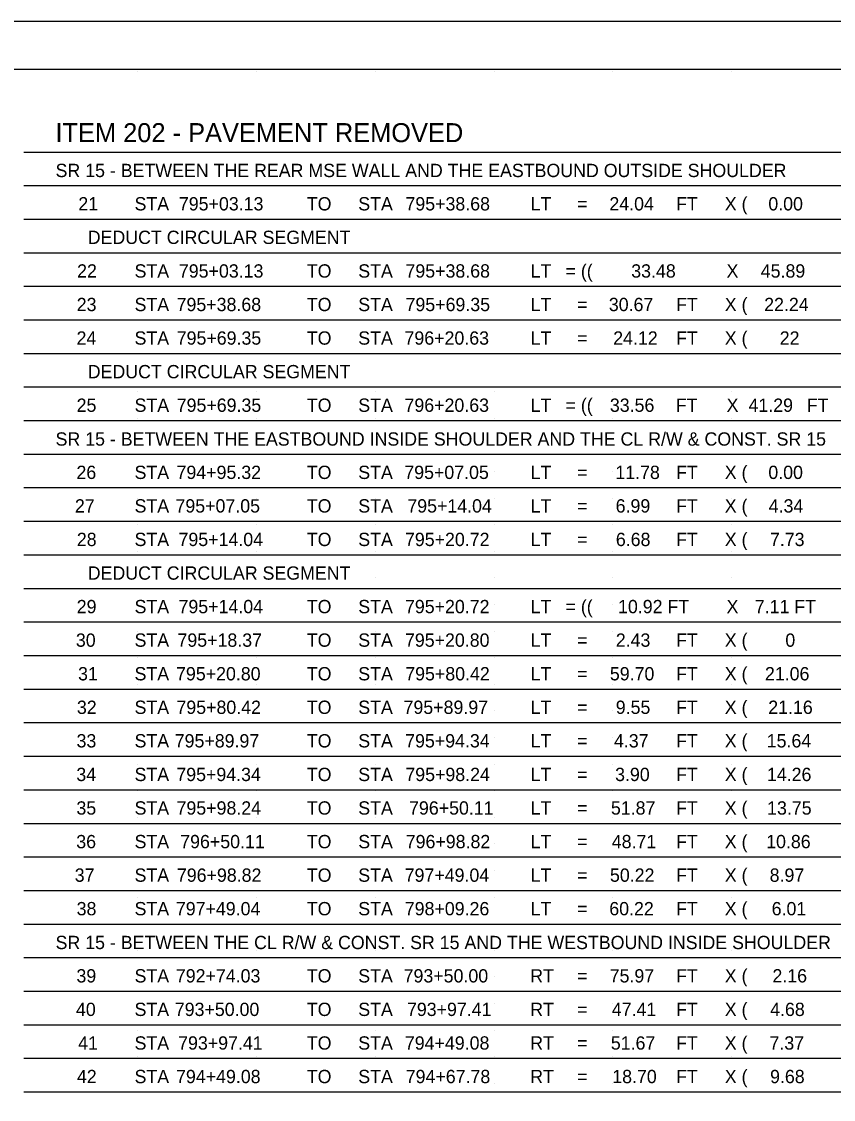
# Model space of a CAD drawing. Extents: x 2073163.5 to 2073197.5, y 634076.4 to 634098.4.
# Drawn here: x 2073180.34 to 2073188.9, y 634087.09 to 634098.43 of the extents above; entities that cross this region are included whole.
import ezdxf

# ---------------------------------------------------------------- set-up
doc = ezdxf.new("R2010")
doc.units = 0
for name, color, linetype in [('SC_Scratch1', 7, 'Continuous'), ('SH_Border', 7, 'Continuous'), ('SH_Cut_Line', 7, 'Continuous'), ('SH_Data', 7, 'Continuous'), ('SH_Text', 7, 'Continuous')]:
    doc.layers.add(name, color=color, linetype=linetype)

msp = doc.modelspace()

# ---------------------------------------------------------------- linework, layer by layer
at = {"layer": 'SC_Scratch1'}
for p, q in [((2073180.369, 634097.061), (2073194.796, 634097.061)), ((2073180.369, 634096.708), (2073194.796, 634096.708)), ((2073180.369, 634096.354), (2073194.796, 634096.354)), ((2073180.369, 634096.001), (2073194.796, 634096.001)), ((2073180.369, 634095.648), (2073194.796, 634095.648)), ((2073180.369, 634095.294), (2073194.796, 634095.294)), ((2073180.369, 634094.941), (2073194.796, 634094.941)), ((2073180.369, 634094.588), (2073194.796, 634094.588)), ((2073180.369, 634094.234), (2073194.796, 634094.234)), ((2073180.369, 634093.881), (2073194.796, 634093.881)), ((2073180.369, 634093.528), (2073194.796, 634093.528)), ((2073180.369, 634093.174), (2073194.796, 634093.174)), ((2073180.369, 634092.821), (2073194.796, 634092.821)), ((2073180.369, 634092.468), (2073194.796, 634092.468)), ((2073180.369, 634092.114), (2073194.796, 634092.114)), ((2073180.369, 634091.761), (2073194.796, 634091.761)), ((2073180.369, 634091.407), (2073194.796, 634091.407)), ((2073180.369, 634091.054), (2073194.796, 634091.054)), ((2073180.369, 634090.701), (2073194.796, 634090.701)), ((2073180.369, 634090.347), (2073194.796, 634090.347)), ((2073180.369, 634089.994), (2073194.796, 634089.994)), ((2073180.369, 634089.641), (2073194.796, 634089.641)), ((2073180.369, 634089.287), (2073194.796, 634089.287)), ((2073180.369, 634088.934), (2073194.796, 634088.934)), ((2073180.369, 634088.581), (2073194.796, 634088.581)), ((2073180.369, 634088.227), (2073194.796, 634088.227)), ((2073180.369, 634087.874), (2073194.796, 634087.874)), ((2073180.369, 634087.521), (2073194.796, 634087.521)), ((2073180.369, 634087.167), (2073194.796, 634087.167))]:
    msp.add_line(p, q, dxfattribs=at)
at = {"layer": 'SH_Border'}
msp.add_lwpolyline([(2073165.007, 634097.934), (2073197.007, 634097.934), (2073197.007, 634076.934), (2073165.007, 634076.934)], close=True, dxfattribs=at)
at = {"layer": 'SH_Cut_Line'}
msp.add_lwpolyline([(2073163.507, 634076.434), (2073197.507, 634076.434), (2073197.507, 634098.434), (2073163.507, 634098.434)], close=True, dxfattribs=at)
at = {"layer": 'SH_Data'}
for p, q in [((2073181.571, 634097.91), (2073181.571, 634097.91)), ((2073181.571, 634097.91), (2073181.571, 634097.91)), ((2073182.821, 634097.91), (2073182.821, 634097.91)), ((2073182.821, 634097.91), (2073182.821, 634097.91)), ((2073182.821, 634097.91), (2073182.821, 634097.91)), ((2073184.071, 634097.91), (2073184.071, 634097.91)), ((2073184.071, 634097.91), (2073184.071, 634097.91)), ((2073184.071, 634097.91), (2073184.071, 634097.91)), ((2073184.071, 634097.91), (2073184.071, 634097.91)), ((2073185.321, 634097.91), (2073185.321, 634097.91)), ((2073185.321, 634097.91), (2073185.321, 634097.91)), ((2073185.321, 634097.91), (2073185.321, 634097.91)), ((2073185.321, 634097.91), (2073185.321, 634097.91)), ((2073185.321, 634097.91), (2073185.321, 634097.91)), ((2073186.571, 634097.91), (2073186.571, 634097.91)), ((2073187.821, 634097.91), (2073187.821, 634097.91)), ((2073181.571, 634094.538), (2073181.571, 634094.538)), ((2073181.571, 634094.538), (2073181.571, 634094.538)), ((2073182.821, 634094.538), (2073182.821, 634094.538)), ((2073182.821, 634094.538), (2073182.821, 634094.538)), ((2073182.821, 634094.538), (2073182.821, 634094.538)), ((2073184.071, 634094.538), (2073184.071, 634094.538)), ((2073184.071, 634094.538), (2073184.071, 634094.538)), ((2073184.071, 634094.538), (2073184.071, 634094.538)), ((2073184.071, 634094.538), (2073184.071, 634094.538)), ((2073185.321, 634094.538), (2073185.321, 634094.538)), ((2073185.321, 634094.538), (2073185.321, 634094.538)), ((2073185.321, 634094.538), (2073185.321, 634094.538)), ((2073185.321, 634094.538), (2073185.321, 634094.538)), ((2073185.321, 634094.538), (2073185.321, 634094.538)), ((2073186.571, 634094.538), (2073186.571, 634094.538)), ((2073187.821, 634094.538), (2073187.821, 634094.538)), ((2073181.571, 634094.258), (2073181.571, 634094.258)), ((2073182.821, 634094.258), (2073182.821, 634094.258)), ((2073184.071, 634094.258), (2073184.071, 634094.258)), ((2073185.321, 634094.258), (2073185.321, 634094.258)), ((2073186.571, 634094.258), (2073186.571, 634094.258)), ((2073187.821, 634094.258), (2073187.821, 634094.258)), ((2073181.571, 634093.978), (2073181.571, 634093.978)), ((2073182.821, 634093.978), (2073182.821, 634093.978)), ((2073184.071, 634093.978), (2073184.071, 634093.978)), ((2073185.321, 634093.978), (2073185.321, 634093.978)), ((2073186.571, 634093.978), (2073186.571, 634093.978)), ((2073187.821, 634093.978), (2073187.821, 634093.978)), ((2073181.571, 634093.698), (2073181.571, 634093.698)), ((2073182.821, 634093.698), (2073182.821, 634093.698)), ((2073184.071, 634093.698), (2073184.071, 634093.698)), ((2073185.321, 634093.698), (2073185.321, 634093.698)), ((2073186.571, 634093.698), (2073186.571, 634093.698)), ((2073187.821, 634093.698), (2073187.821, 634093.698)), ((2073181.571, 634093.418), (2073181.571, 634093.418)), ((2073182.821, 634093.418), (2073182.821, 634093.418)), ((2073184.071, 634093.418), (2073184.071, 634093.418)), ((2073185.321, 634093.418), (2073185.321, 634093.418)), ((2073186.571, 634093.418), (2073186.571, 634093.418)), ((2073187.821, 634093.418), (2073187.821, 634093.418)), ((2073181.571, 634093.138), (2073181.571, 634093.138)), ((2073182.821, 634093.138), (2073182.821, 634093.138)), ((2073184.071, 634093.138), (2073184.071, 634093.138)), ((2073185.321, 634093.138), (2073185.321, 634093.138)), ((2073186.571, 634093.138), (2073186.571, 634093.138)), ((2073187.821, 634093.138), (2073187.821, 634093.138)), ((2073181.571, 634092.858), (2073181.571, 634092.858)), ((2073182.821, 634092.858), (2073182.821, 634092.858)), ((2073184.071, 634092.858), (2073184.071, 634092.858)), ((2073185.321, 634092.858), (2073185.321, 634092.858)), ((2073186.571, 634092.858), (2073186.571, 634092.858)), ((2073187.821, 634092.858), (2073187.821, 634092.858)), ((2073181.571, 634092.578), (2073181.571, 634092.578)), ((2073182.821, 634092.578), (2073182.821, 634092.578)), ((2073184.071, 634092.578), (2073184.071, 634092.578)), ((2073185.321, 634092.578), (2073185.321, 634092.578)), ((2073186.571, 634092.578), (2073186.571, 634092.578)), ((2073187.821, 634092.578), (2073187.821, 634092.578)), ((2073181.571, 634092.298), (2073181.571, 634092.298)), ((2073182.821, 634092.298), (2073182.821, 634092.298)), ((2073184.071, 634092.298), (2073184.071, 634092.298)), ((2073185.321, 634092.298), (2073185.321, 634092.298)), ((2073186.571, 634092.298), (2073186.571, 634092.298)), ((2073187.821, 634092.298), (2073187.821, 634092.298)), ((2073181.571, 634092.018), (2073181.571, 634092.018)), ((2073182.821, 634092.018), (2073182.821, 634092.018)), ((2073184.071, 634092.018), (2073184.071, 634092.018)), ((2073185.321, 634092.018), (2073185.321, 634092.018)), ((2073186.571, 634092.018), (2073186.571, 634092.018)), ((2073187.821, 634092.018), (2073187.821, 634092.018)), ((2073181.571, 634091.738), (2073181.571, 634091.738)), ((2073182.821, 634091.738), (2073182.821, 634091.738)), ((2073184.071, 634091.738), (2073184.071, 634091.738)), ((2073185.321, 634091.738), (2073185.321, 634091.738)), ((2073186.571, 634091.738), (2073186.571, 634091.738)), ((2073187.821, 634091.738), (2073187.821, 634091.738)), ((2073181.571, 634091.458), (2073181.571, 634091.458)), ((2073182.821, 634091.458), (2073182.821, 634091.458)), ((2073184.071, 634091.458), (2073184.071, 634091.458)), ((2073185.321, 634091.458), (2073185.321, 634091.458)), ((2073186.571, 634091.458), (2073186.571, 634091.458)), ((2073187.821, 634091.458), (2073187.821, 634091.458)), ((2073181.571, 634091.178), (2073181.571, 634091.178)), ((2073182.821, 634091.178), (2073182.821, 634091.178)), ((2073184.071, 634091.178), (2073184.071, 634091.178)), ((2073185.321, 634091.178), (2073185.321, 634091.178)), ((2073186.571, 634091.178), (2073186.571, 634091.178)), ((2073187.821, 634091.178), (2073187.821, 634091.178)), ((2073181.571, 634090.898), (2073181.571, 634090.898)), ((2073182.821, 634090.898), (2073182.821, 634090.898)), ((2073184.071, 634090.898), (2073184.071, 634090.898)), ((2073185.321, 634090.898), (2073185.321, 634090.898)), ((2073186.571, 634090.898), (2073186.571, 634090.898)), ((2073187.821, 634090.898), (2073187.821, 634090.898)), ((2073181.571, 634090.618), (2073181.571, 634090.618)), ((2073182.821, 634090.618), (2073182.821, 634090.618)), ((2073184.071, 634090.618), (2073184.071, 634090.618)), ((2073185.321, 634090.618), (2073185.321, 634090.618)), ((2073186.571, 634090.618), (2073186.571, 634090.618)), ((2073187.821, 634090.618), (2073187.821, 634090.618)), ((2073181.571, 634090.338), (2073181.571, 634090.338)), ((2073182.821, 634090.338), (2073182.821, 634090.338)), ((2073184.071, 634090.338), (2073184.071, 634090.338)), ((2073185.321, 634090.338), (2073185.321, 634090.338)), ((2073186.571, 634090.338), (2073186.571, 634090.338)), ((2073187.821, 634090.338), (2073187.821, 634090.338)), ((2073181.571, 634090.058), (2073181.571, 634090.058)), ((2073182.821, 634090.058), (2073182.821, 634090.058)), ((2073184.071, 634090.058), (2073184.071, 634090.058)), ((2073185.321, 634090.058), (2073185.321, 634090.058)), ((2073186.571, 634090.058), (2073186.571, 634090.058)), ((2073187.821, 634090.058), (2073187.821, 634090.058)), ((2073181.571, 634089.778), (2073181.571, 634089.778)), ((2073182.821, 634089.778), (2073182.821, 634089.778)), ((2073184.071, 634089.778), (2073184.071, 634089.778)), ((2073185.321, 634089.778), (2073185.321, 634089.778)), ((2073186.571, 634089.778), (2073186.571, 634089.778)), ((2073187.821, 634089.778), (2073187.821, 634089.778)), ((2073181.571, 634089.498), (2073181.571, 634089.498)), ((2073182.821, 634089.498), (2073182.821, 634089.498)), ((2073184.071, 634089.498), (2073184.071, 634089.498)), ((2073185.321, 634089.498), (2073185.321, 634089.498)), ((2073186.571, 634089.498), (2073186.571, 634089.498)), ((2073187.821, 634089.498), (2073187.821, 634089.498)), ((2073181.571, 634089.218), (2073181.571, 634089.218)), ((2073182.821, 634089.218), (2073182.821, 634089.218)), ((2073184.071, 634089.218), (2073184.071, 634089.218)), ((2073185.321, 634089.218), (2073185.321, 634089.218)), ((2073186.571, 634089.218), (2073186.571, 634089.218)), ((2073187.821, 634089.218), (2073187.821, 634089.218)), ((2073181.571, 634088.938), (2073181.571, 634088.938)), ((2073182.821, 634088.938), (2073182.821, 634088.938)), ((2073184.071, 634088.938), (2073184.071, 634088.938)), ((2073185.321, 634088.938), (2073185.321, 634088.938)), ((2073186.571, 634088.938), (2073186.571, 634088.938)), ((2073187.821, 634088.938), (2073187.821, 634088.938)), ((2073181.571, 634088.658), (2073181.571, 634088.658)), ((2073182.821, 634088.658), (2073182.821, 634088.658)), ((2073184.071, 634088.658), (2073184.071, 634088.658)), ((2073185.321, 634088.658), (2073185.321, 634088.658)), ((2073186.571, 634088.658), (2073186.571, 634088.658)), ((2073187.821, 634088.658), (2073187.821, 634088.658)), ((2073181.571, 634088.378), (2073181.571, 634088.378)), ((2073182.821, 634088.378), (2073182.821, 634088.378)), ((2073184.071, 634088.378), (2073184.071, 634088.378)), ((2073185.321, 634088.378), (2073185.321, 634088.378)), ((2073186.571, 634088.378), (2073186.571, 634088.378)), ((2073187.821, 634088.378), (2073187.821, 634088.378)), ((2073181.571, 634088.098), (2073181.571, 634088.098)), ((2073182.821, 634088.098), (2073182.821, 634088.098)), ((2073184.071, 634088.098), (2073184.071, 634088.098)), ((2073185.321, 634088.098), (2073185.321, 634088.098)), ((2073186.571, 634088.098), (2073186.571, 634088.098)), ((2073187.821, 634088.098), (2073187.821, 634088.098)), ((2073181.571, 634087.818), (2073181.571, 634087.818)), ((2073182.821, 634087.818), (2073182.821, 634087.818)), ((2073184.071, 634087.818), (2073184.071, 634087.818)), ((2073185.321, 634087.818), (2073185.321, 634087.818)), ((2073186.571, 634087.818), (2073186.571, 634087.818)), ((2073187.821, 634087.818), (2073187.821, 634087.818)), ((2073181.571, 634087.538), (2073181.571, 634087.538)), ((2073182.821, 634087.538), (2073182.821, 634087.538)), ((2073184.071, 634087.538), (2073184.071, 634087.538)), ((2073185.321, 634087.538), (2073185.321, 634087.538)), ((2073186.571, 634087.538), (2073186.571, 634087.538)), ((2073187.821, 634087.538), (2073187.821, 634087.538)), ((2073181.571, 634087.258), (2073181.571, 634087.258)), ((2073182.821, 634087.258), (2073182.821, 634087.258)), ((2073184.071, 634087.258), (2073184.071, 634087.258)), ((2073185.321, 634087.258), (2073185.321, 634087.258)), ((2073186.571, 634087.258), (2073186.571, 634087.258)), ((2073187.821, 634087.258), (2073187.821, 634087.258))]:
    msp.add_line(p, q, dxfattribs=at)

# ---------------------------------------------------------------- texts
msp.add_text('ITEM 202 - PAVEMENT REMOVED', height=0.2, dxfattribs=at).set_placement((2073180.702, 634097.165))
at = {"layer": 'SH_Text'}
for s, p in [('SR 15 - BETWEEN THE REAR MSE WALL AND THE EASTBOUND OUTSIDE SHOULDER', (2073180.703, 634096.797)), ('21', (2073180.943, 634096.446)), ('STA', (2073181.535, 634096.446)), ('795+03.13', (2073182.002, 634096.446)), ('TO', (2073183.349, 634096.446)), ('STA', (2073183.891, 634096.446)), ('795+38.68', (2073184.388, 634096.446)), ('LT', (2073185.706, 634096.446)), ('=', (2073186.196, 634096.446)), ('24.04', (2073186.536, 634096.446)), ('FT', (2073187.238, 634096.446)), ('X (', (2073187.751, 634096.446)), ('0.00', (2073188.21, 634096.446)), ('DEDUCT CIRCULAR SEGMENT', (2073181.042, 634096.093)), ('22', (2073180.93, 634095.739)), ('STA', (2073181.535, 634095.739)), ('795+03.13', (2073182.002, 634095.739)), ('TO', (2073183.349, 634095.739)), ('STA', (2073183.891, 634095.739)), ('795+38.68', (2073184.388, 634095.739)), ('LT', (2073185.706, 634095.739)), ('= ((', (2073186.074, 634095.739)), ('33.48', (2073186.766, 634095.739)), ('X', (2073187.77, 634095.739)), ('45.89', (2073188.13, 634095.739)), ('23', (2073180.926, 634095.386)), ('STA', (2073181.535, 634095.386)), ('795+38.68', (2073181.978, 634095.386)), ('TO', (2073183.349, 634095.386)), ('STA', (2073183.891, 634095.386)), ('795+69.35', (2073184.389, 634095.386)), ('LT', (2073185.706, 634095.386)), ('=', (2073186.196, 634095.386)), ('30.67', (2073186.53, 634095.386)), ('FT', (2073187.238, 634095.386)), ('X (', (2073187.751, 634095.386)), ('22.24', (2073188.166, 634095.386)), ('24', (2073180.924, 634095.033)), ('STA', (2073181.535, 634095.033)), ('795+69.35', (2073181.979, 634095.033)), ('TO', (2073183.349, 634095.033)), ('STA', (2073183.891, 634095.033)), ('796+20.63', (2073184.378, 634095.033)), ('LT', (2073185.706, 634095.033)), ('24.12', (2073186.576, 634095.033)), ('FT', (2073187.238, 634095.033)), ('X (', (2073187.751, 634095.033)), ('22', (2073188.33, 634095.033)), ('=', (2073186.196, 634095.033)), ('DEDUCT CIRCULAR SEGMENT', (2073181.042, 634094.679)), ('25', (2073180.925, 634094.326)), ('STA', (2073181.535, 634094.326)), ('795+69.35', (2073181.979, 634094.326)), ('TO', (2073183.349, 634094.326)), ('STA', (2073183.891, 634094.326)), ('796+20.63', (2073184.378, 634094.326)), ('LT', (2073185.706, 634094.326)), ('= ((', (2073186.074, 634094.326)), ('33.56', (2073186.541, 634094.326)), ('FT', (2073187.235, 634094.326)), ('X', (2073187.77, 634094.326)), ('41.29', (2073188.001, 634094.326)), ('FT', (2073188.615, 634094.326)), ('SR 15 - BETWEEN THE EASTBOUND INSIDE SHOULDER AND THE CL R/W & CONST. SR 15', (2073180.703, 634093.97)), ('26', (2073180.923, 634093.619)), ('STA', (2073181.535, 634093.619)), ('794+95.32', (2073181.977, 634093.619)), ('TO', (2073183.349, 634093.619)), ('STA', (2073183.891, 634093.619)), ('795+07.05', (2073184.376, 634093.619)), ('LT', (2073185.706, 634093.619)), ('=', (2073186.196, 634093.619)), ('11.78', (2073186.599, 634093.619)), ('FT', (2073187.238, 634093.619)), ('X (', (2073187.751, 634093.619)), ('0.00', (2073188.21, 634093.619)), ('27', (2073180.907, 634093.266)), ('STA', (2073181.535, 634093.266)), ('795+07.05', (2073181.966, 634093.266)), ('TO', (2073183.349, 634093.266)), ('STA', (2073183.891, 634093.266)), ('795+14.04', (2073184.408, 634093.266)), ('LT', (2073185.706, 634093.266)), ('=', (2073186.196, 634093.266)), ('6.99', (2073186.602, 634093.266)), ('FT', (2073187.238, 634093.266)), ('X (', (2073187.751, 634093.266)), ('4.34', (2073188.214, 634093.266)), ('28', (2073180.927, 634092.913)), ('STA', (2073181.535, 634092.913)), ('795+14.04', (2073181.998, 634092.913)), ('TO', (2073183.349, 634092.913)), ('STA', (2073183.891, 634092.913)), ('795+20.72', (2073184.383, 634092.913)), ('LT', (2073185.706, 634092.913)), ('=', (2073186.196, 634092.913)), ('6.68', (2073186.604, 634092.913)), ('FT', (2073187.238, 634092.913)), ('X (', (2073187.751, 634092.913)), ('7.73', (2073188.227, 634092.913)), ('DEDUCT CIRCULAR SEGMENT', (2073181.042, 634092.559)), ('29', (2073180.926, 634092.206)), ('STA', (2073181.535, 634092.206)), ('795+14.04', (2073181.998, 634092.206)), ('TO', (2073183.349, 634092.206)), ('STA', (2073183.891, 634092.206)), ('795+20.72', (2073184.383, 634092.206)), ('LT', (2073185.706, 634092.206)), ('= ((', (2073186.074, 634092.206)), ('10.92 FT', (2073186.627, 634092.206)), ('X', (2073187.77, 634092.206)), ('7.11 FT', (2073188.067, 634092.206)), ('30', (2073180.917, 634091.853)), ('STA', (2073181.535, 634091.853)), ('795+18.37', (2073181.987, 634091.853)), ('TO', (2073183.349, 634091.853)), ('STA', (2073183.891, 634091.853)), ('795+20.80', (2073184.383, 634091.853)), ('LT', (2073185.706, 634091.853)), ('2.43', (2073186.603, 634091.853)), ('FT', (2073187.238, 634091.853)), ('X (', (2073187.751, 634091.853)), ('0', (2073188.389, 634091.853)), ('=', (2073186.196, 634091.853)), ('31', (2073180.94, 634091.499)), ('STA', (2073181.535, 634091.499)), ('795+20.80', (2073181.972, 634091.499)), ('TO', (2073183.349, 634091.499)), ('STA', (2073183.891, 634091.499)), ('795+80.42', (2073184.386, 634091.499)), ('LT', (2073185.706, 634091.499)), ('59.70', (2073186.541, 634091.499)), ('FT', (2073187.238, 634091.499)), ('X (', (2073187.751, 634091.499)), ('21.06', (2073188.174, 634091.499)), ('=', (2073186.196, 634091.499)), ('32', (2073180.928, 634091.146)), ('STA', (2073181.535, 634091.146)), ('795+80.42', (2073181.976, 634091.146)), ('TO', (2073183.349, 634091.146)), ('STA', (2073183.891, 634091.146)), ('795+89.97', (2073184.368, 634091.146)), ('LT', (2073185.706, 634091.146)), ('9.55', (2073186.603, 634091.146)), ('FT', (2073187.238, 634091.146)), ('X (', (2073187.751, 634091.146)), ('21.16', (2073188.209, 634091.146)), ('=', (2073186.196, 634091.146)), ('33', (2073180.924, 634090.793)), ('STA', (2073181.535, 634090.793)), ('795+89.97', (2073181.958, 634090.793)), ('TO', (2073183.349, 634090.793)), ('STA', (2073183.891, 634090.793)), ('795+94.34', (2073184.385, 634090.793)), ('LT', (2073185.706, 634090.793)), ('=', (2073186.196, 634090.793)), ('4.37', (2073186.584, 634090.793)), ('FT', (2073187.238, 634090.793)), ('X (', (2073187.751, 634090.793)), ('15.64', (2073188.193, 634090.793)), ('34', (2073180.922, 634090.439)), ('STA', (2073181.535, 634090.439)), ('795+94.34', (2073181.975, 634090.439)), ('TO', (2073183.349, 634090.439)), ('STA', (2073183.891, 634090.439)), ('795+98.24', (2073184.387, 634090.439)), ('LT', (2073185.706, 634090.439)), ('=', (2073186.196, 634090.439)), ('3.90', (2073186.596, 634090.439)), ('FT', (2073187.238, 634090.439)), ('X (', (2073187.751, 634090.439)), ('14.26', (2073188.195, 634090.439)), ('35', (2073180.923, 634090.086)), ('STA', (2073181.535, 634090.086)), ('795+98.24', (2073181.977, 634090.086)), ('TO', (2073183.349, 634090.086)), ('STA', (2073183.891, 634090.086)), ('796+50.11', (2073184.426, 634090.086)), ('LT', (2073185.706, 634090.086)), ('=', (2073186.196, 634090.086)), ('51.87', (2073186.552, 634090.086)), ('FT', (2073187.238, 634090.086)), ('X (', (2073187.751, 634090.086)), ('13.75', (2073188.197, 634090.086)), ('36', (2073180.921, 634089.732)), ('STA', (2073181.535, 634089.732)), ('796+50.11', (2073182.016, 634089.732)), ('TO', (2073183.349, 634089.732)), ('STA', (2073183.891, 634089.732)), ('796+98.82', (2073184.391, 634089.732)), ('LT', (2073185.706, 634089.732)), ('=', (2073186.196, 634089.732)), ('48.71', (2073186.561, 634089.732)), ('FT', (2073187.238, 634089.732)), ('X (', (2073187.751, 634089.732)), ('10.86', (2073188.187, 634089.732)), ('37', (2073180.905, 634089.379)), ('STA', (2073181.535, 634089.379)), ('796+98.82', (2073181.981, 634089.379)), ('TO', (2073183.349, 634089.379)), ('STA', (2073183.891, 634089.379)), ('797+49.04', (2073184.38, 634089.379)), ('LT', (2073185.706, 634089.379)), ('=', (2073186.196, 634089.379)), ('50.22', (2073186.542, 634089.379)), ('FT', (2073187.238, 634089.379)), ('X (', (2073187.751, 634089.379)), ('8.97', (2073188.224, 634089.379)), ('38', (2073180.925, 634089.026)), ('STA', (2073181.535, 634089.026)), ('797+49.04', (2073181.97, 634089.026)), ('TO', (2073183.349, 634089.026)), ('STA', (2073183.891, 634089.026)), ('798+09.26', (2073184.381, 634089.026)), ('LT', (2073185.706, 634089.026)), ('60.22', (2073186.535, 634089.026)), ('FT', (2073187.238, 634089.026)), ('X (', (2073187.751, 634089.026)), ('6.01', (2073188.245, 634089.026)), ('=', (2073186.196, 634089.026)), ('SR 15 - BETWEEN THE CL R/W & CONST. SR 15 AND THE WESTBOUND INSIDE SHOULDER', (2073180.703, 634088.67)), ('39', (2073180.923, 634088.319)), ('STA', (2073181.535, 634088.319)), ('792+74.03', (2073181.97, 634088.319)), ('TO', (2073183.349, 634088.319)), ('STA', (2073183.891, 634088.319)), ('793+50.00', (2073184.369, 634088.319)), ('RT', (2073185.702, 634088.319)), ('75.97', (2073186.539, 634088.319)), ('FT', (2073187.238, 634088.319)), ('X (', (2073187.751, 634088.319)), ('2.16', (2073188.253, 634088.319)), ('=', (2073186.196, 634088.319)), ('X (', (2073187.751, 634087.966)), ('40', (2073180.918, 634087.966)), ('STA', (2073181.535, 634087.966)), ('793+50.00', (2073181.959, 634087.966)), ('TO', (2073183.349, 634087.966)), ('STA', (2073183.891, 634087.966)), ('793+97.41', (2073184.404, 634087.966)), ('RT', (2073185.702, 634087.966)), ('=', (2073186.196, 634087.966)), ('47.41', (2073186.561, 634087.966)), ('FT', (2073187.238, 634087.966)), ('4.68', (2073188.229, 634087.966)), ('41', (2073180.941, 634087.612)), ('STA', (2073181.535, 634087.612)), ('793+97.41', (2073181.994, 634087.612)), ('TO', (2073183.349, 634087.612)), ('STA', (2073183.891, 634087.612)), ('794+49.08', (2073184.382, 634087.612)), ('RT', (2073185.702, 634087.612)), ('=', (2073186.196, 634087.612)), ('51.67', (2073186.551, 634087.612)), ('FT', (2073187.238, 634087.612)), ('X (', (2073187.751, 634087.612)), ('7.37', (2073188.222, 634087.612)), ('42', (2073180.928, 634087.259)), ('STA', (2073181.535, 634087.259)), ('794+49.08', (2073181.972, 634087.259)), ('TO', (2073183.349, 634087.259)), ('STA', (2073183.891, 634087.259)), ('794+67.78', (2073184.391, 634087.259)), ('RT', (2073185.702, 634087.259)), ('=', (2073186.196, 634087.259)), ('18.70', (2073186.566, 634087.259)), ('FT', (2073187.238, 634087.259)), ('X (', (2073187.751, 634087.259)), ('9.68', (2073188.228, 634087.259))]:
    msp.add_text(s, height=0.14, rotation=0.0001, dxfattribs=at).set_placement(p)

doc.saveas('drawing.dxf')
